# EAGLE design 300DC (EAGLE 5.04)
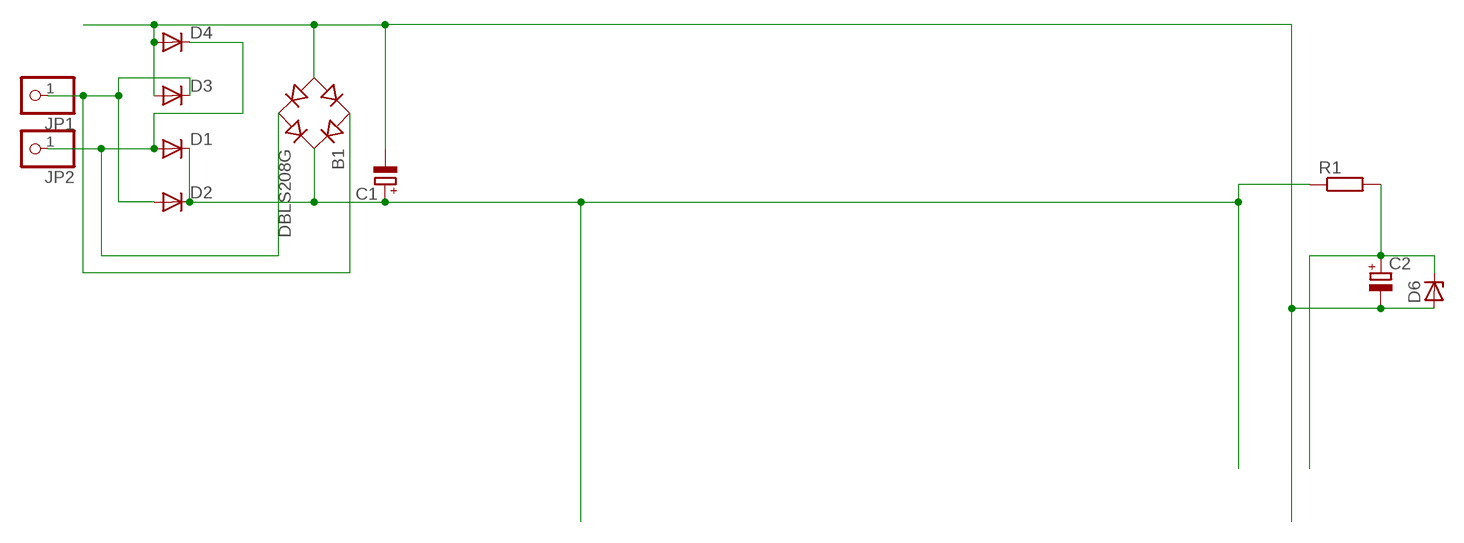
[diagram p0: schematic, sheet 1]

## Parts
B1  DBLS208G  [DBS]
C1  CPOL-EUE5-8.5  [E5-8,5]
C2  CPOL-EUE5-5  [E5-5]
D1  DIODE-DO35-10  [DO35-10]
D2  DIODE-D-5  [D-5]
D3  DIODE-DO35-10  [DO35-10]
D4  DIODE-D-5  [D-5]
D6  ZENER-DIODEZD-5  [ZDIO-5]
JP1  PINHD-1X1  [1X01]
JP2  PINHD-1X1  [1X01]
R1  R-EU_0204/5  [0204/5]

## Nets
N$1: B1.- C1.- C2.- D3.A D4.A D6.A
N$2: B1.+ C1.+ D1.C D2.C R1.1
N$3: B1.AC1 D2.A D3.C JP1.1
N$4: B1.AC2 D1.A D4.C JP2.1
N$5: C2.+ D6.C R1.2

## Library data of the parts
B1 = rectifier:DB?*G: Single Phase 1.0 AMP Glass Passivated Bridge Rectifier Taiwan Semiconductor Co.,Ltd. - TSC Source: http://www.taiwansemi.com/TSCbig5/ezcatfiles/cust/img/img/db101g.pdf http://www.ts.com.tw/db/pictures/modules/PDT/PDT060207001/DBLS201G.pdf
C1 C2 = rcl-2:CPOL-EU: POLARIZED CAPACITOR, European symbol
D1-D4 = diode-1:DIODE-: DIODE
D6 = diode-1:ZENER-DIODE: Z-Diode
JP1 JP2 = pinhead:PINHD-1X1: PIN HEADER
R1 = rcl-2:R-EU_: RESISTOR, European symbol

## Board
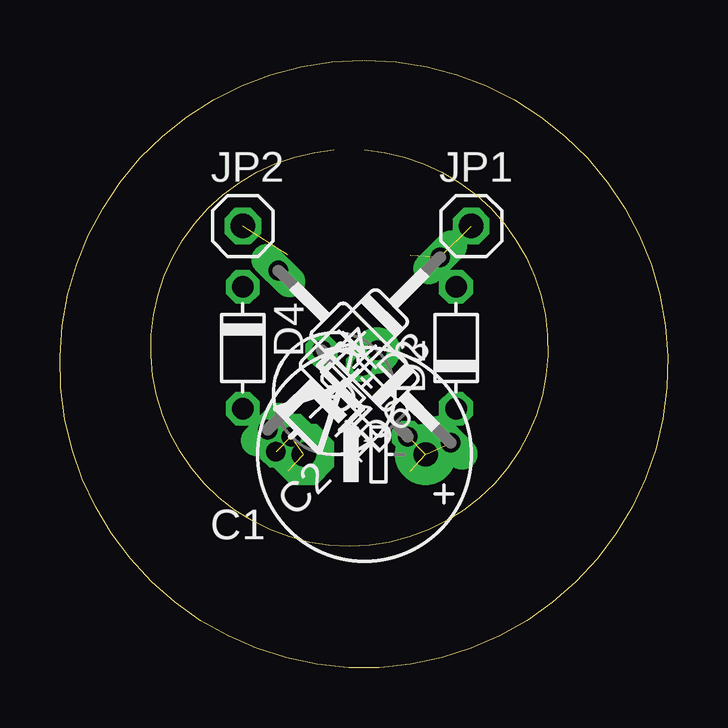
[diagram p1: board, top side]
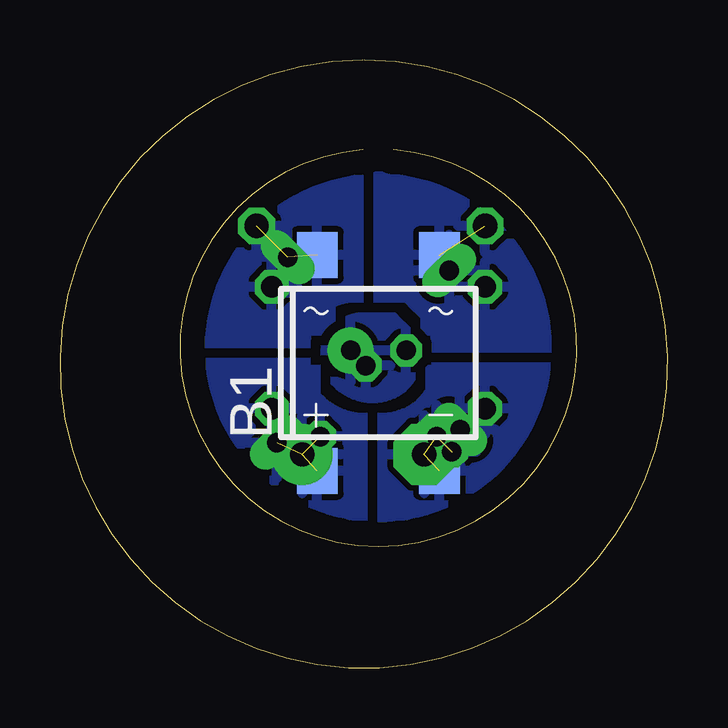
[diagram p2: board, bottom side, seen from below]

Size 25.35 x 25.34 mm. Coordinates in mm from the lower left corner, seen from the top.
Outline: 12.7,25.34 arc-360 12.64,25.34
Outline: 12.7,21.59 arc-351 11.43,21.59
Copper layers (1*16): Top 0.035mm / dielectric 1.5mm / Bottom 0.035mm
Design rules "default": minimum track width 10mil, minimum drill 24mil, track to track 8mil, track to pad 8mil, pad to pad 8mil, via to via 8mil, smd to smd 8mil, copper to edge 40mil, drill to drill 8mil, minimum pad ring 10mil, minimum via ring 8mil, stop-mask expansion 4mil, vias tented up to drill 0mil, thermal gap 10mil

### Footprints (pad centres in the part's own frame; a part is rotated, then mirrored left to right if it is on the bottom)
DBS = smd 1.7 x 1.9: + -2.55,-4.5; - 2.55,-4.5; AC1 -2.55,4.5; AC2 2.55,4.5
E5-8,5 = drill 1.016 pad 2.54 round: + -2.54,0 | drill 1.016 pad 2.54 octagon: - 2.54,0
E5-5 = drill 0.813 pad 1.905 round: + -2.54,0 | drill 0.813 pad 1.905 octagon: - 2.54,0
DO35-10 = drill 0.813 long: A 5.08,0; C -5.08,0
D-5 = drill 0.9 octagon: A 2.54,0; C -2.54,0
ZDIO-5 = drill 0.813 octagon: A 2.54,0; C -2.54,0
1X01 = drill 1.016 octagon: 1 0,0
0204/5 = drill 0.813 octagon: 1 -2.54,0; 2 2.54,0

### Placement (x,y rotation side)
B1  12.07,12.7 0 bottom
C1  12.7,8.89 180 top
C2  11.43,11.43 225 top
D1  12.7,12.96 135 top
D2  16.51,13.34 90 top
D3  12.26,13.52 225 top
D4  7.62,13.34 270 top
D6  10.8,10.8 225 top
JP1  17.15,18.42 0 top
JP2  7.62,18.42 0 top
R1  12.7,11.43 135 top

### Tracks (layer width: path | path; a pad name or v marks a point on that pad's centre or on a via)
N$1  (3 unrouted)
  pour Bottom (isolate 0.406, rank 3): 1.91,12.7 12.7,12.7 12.7,0.64 6.99,1.91 1.91,6.99
N$2  (3 unrouted)
  pour Bottom (isolate 0.406, rank 2): 12.7,12.7 24.13,12.7 22.23,6.35 17.78,1.91 12.7,1.27
N$3  (2 unrouted)
  pour Bottom (isolate 0.406, rank 3): 12.7,25.4 12.7,12.7 24.77,13.34 23.5,19.69
N$4  (1 unrouted)
  pour Bottom (isolate 0.406, rank 2): 6.35,22.86 2.54,17.78 1.27,13.34 12.07,13.34 12.07,24.13
N$5
  pour Bottom (isolate 0.406): 11.43,14.61 12.7,14.61 arc-127 13.97,12.07 arc-78 11.43,11.43 arc-102 10.8,13.97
